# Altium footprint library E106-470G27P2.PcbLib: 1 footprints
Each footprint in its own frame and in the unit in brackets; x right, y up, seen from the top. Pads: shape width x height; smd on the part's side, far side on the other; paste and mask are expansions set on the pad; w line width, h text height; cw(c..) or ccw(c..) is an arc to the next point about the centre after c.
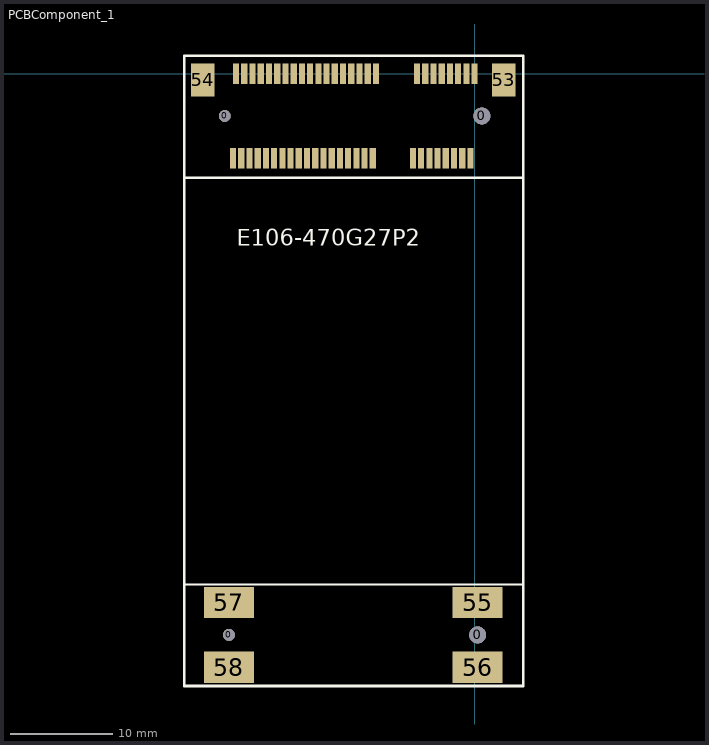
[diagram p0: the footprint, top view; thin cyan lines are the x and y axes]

## PCBComponent_1 [mm]
pads (62):
  round 1.15 hole 1.15 unplated: 0(-24.3,-4.1) 0(-23.9,-54.585)
  round 1.65 hole 1.65 unplated: 0(0.3,-54.585) 0(0.7,-4.1)
  rect 0.6x2 smd: 1(0,0) 2(-0.4,-8.2) 3(-0.8,0) 4(-1.2,-8.2) 5(-1.6,0) 6(-2,-8.2) 7(-2.4,0) 8(-2.8,-8.2) 9(-3.2,0) 10(-3.6,-8.2) 11(-4,0) 12(-4.4,-8.2) 13(-4.8,0) 14(-5.2,-8.2) 15(-5.6,0) 16(-6,-8.2) 17(-9.6,0) 18(-9.9,-8.2) 19(-10.4,0) 20(-10.7,-8.2) 21(-11.2,0) 22(-11.5,-8.2) 23(-12,0) 24(-12.3,-8.2) 25(-12.8,0) 26(-13.1,-8.2) 27(-13.6,0) 28(-13.9,-8.2) 29(-14.4,0) 30(-14.7,-8.2) 31(-15.2,0) 32(-15.5,-8.2) 33(-16,0) 34(-16.3,-8.2) 35(-16.8,0) 36(-17.1,-8.2) 37(-17.6,0) 38(-17.9,-8.2) 39(-18.4,0) 40(-18.7,-8.2) 41(-19.2,0) 42(-19.5,-8.2) 43(-20,0) 44(-20.3,-8.2) 45(-20.8,0) 46(-21.1,-8.2) 47(-21.6,0) 48(-21.9,-8.2) 49(-22.4,0) 50(-22.7,-8.2) 51(-23.2,0) 52(-23.5,-8.2)
  rect 2.3x3.2 smd: 53(2.84,-0.6) 54(-26.45,-0.6)
  rect 4.85x3.05 smd: 55(0.3,-51.435) 56(0.3,-57.735) 57(-23.9,-51.435) 58(-23.9,-57.735)
Top Overlay:
  lines w0.127: -28.176,-49.728 4.799,-49.728 ; -28.176,-49.643 4.799,-49.643
  lines w0.254: -28.26,-49.812 -28.26,-59.563 4.74,-59.563 4.74,-49.787 ; -28.26,-49.643 -28.26,-10.1 ; 4.74,-49.643 4.74,-10.1 ; -28.26,-10.1 -28.26,1.75 4.74,1.75 4.74,-10.1 ; -28.26,-10.1 4.74,-10.1
  text "E106-470G27P2" at -23.151,-16.748 h1.6
3D body "1827682-1.stp": height 5, standoff 0, extent -27.79,-58.928 4.21,-50.428
3D body "2041119-2.stp": height 3.98, standoff -0.67, extent -26.74,-8.582 3.16,0.508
